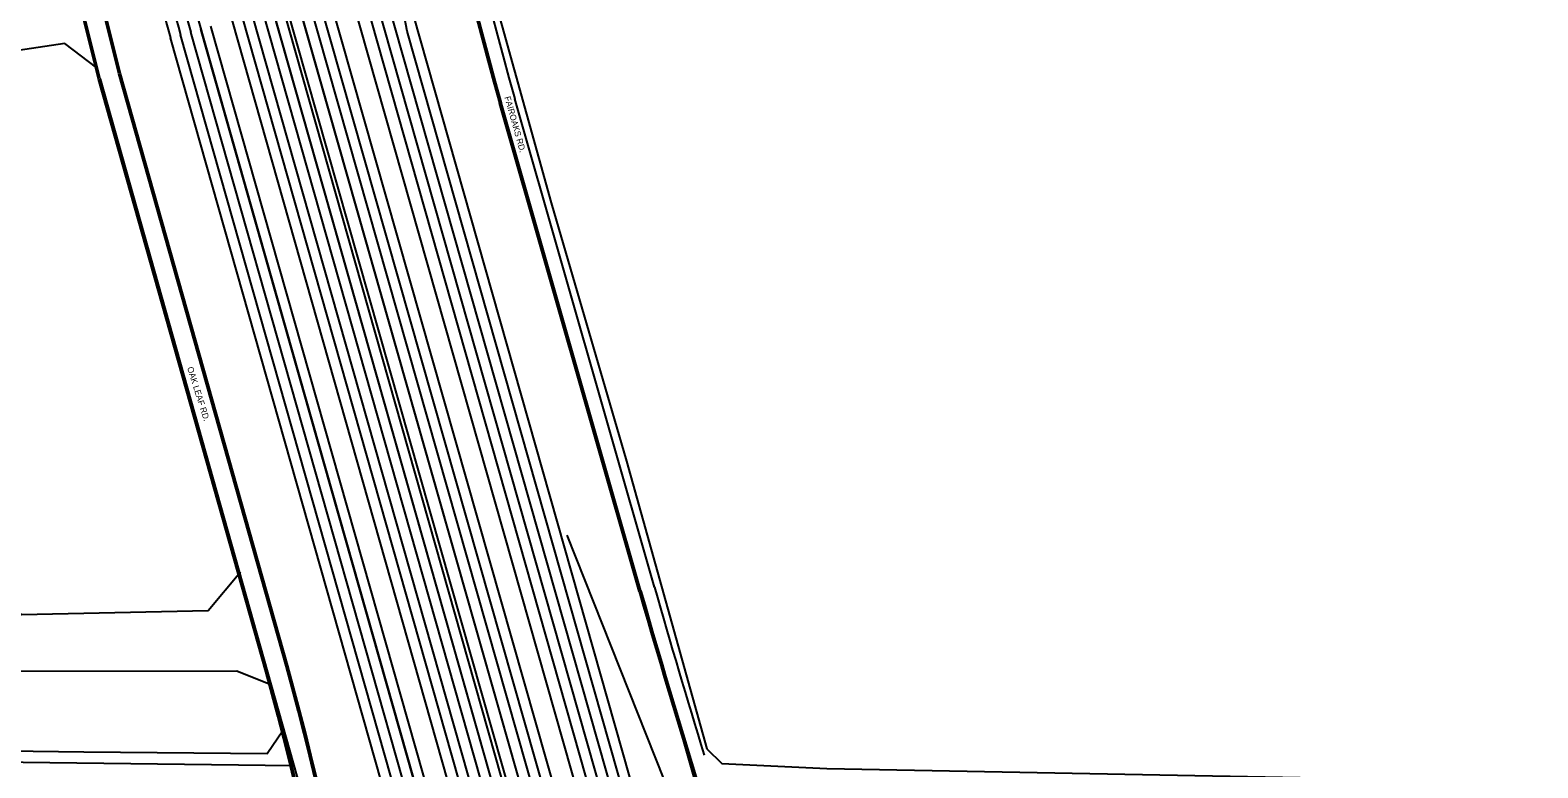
# Model space of a CAD drawing. Extents: x 227157 to 233208, y 434992 to 456232.
# Drawn here: x 228022 to 229741, y 441185 to 442026 of the extents above; entities that cross this region are included whole.
import ezdxf

# ---------------------------------------------------------------- set-up
doc = ezdxf.new("R2010")
doc.units = 0
for name, color, linetype in [('GE_X_Alignment', 7, 'Continuous'), ('PM_X_Edge_Line', 7, 'Continuous'), ('PM_X_Lane_Line', 7, 'Continuous'), ('PV_X_EOP', 7, 'Continuous'), ('SV_X_Text_Name', 7, 'Continuous')]:
    doc.layers.add(name, color=color, linetype=linetype)

msp = doc.modelspace()

# ---------------------------------------------------------------- linework, layer by layer
at = {"layer": 'GE_X_Alignment'}
for p, q in [((229741.1, 437351.7), (227977.9, 443563.5)), ((229633.3, 437464.5), (227927.6, 443466.1)), ((227851.2, 443315.4), (228989, 439305.6)), ((229609.5, 437429.5), (227988.9, 443142.3)), ((228939, 440614.9), (228424.6, 442414.9)), ((228102.1, 441970.7), (228482.9, 440620.6)), ((229099.2, 440282.1), (228634.2, 441450.4))]:
    msp.add_line(p, q, dxfattribs=at)
for centre, radius, start, end in [((232310.4, 443015.6), 3901.3, 184.177, 195.95), ((239163.9, 444372.1), 10863.7, 195.95, 201.69969), ((225496.6, 440506.4), 2905.1, 359.1873, 15.7485)]:
    msp.add_arc(centre, radius, start, end, dxfattribs=at)
at = {"layer": 'PM_X_Edge_Line'}
for p, q in [((228102.1, 441970.7), (228028.1, 442265.3)), ((228123.4, 441976.4), (228055.5, 442246.3)), ((228452, 442025.2), (228432, 442131.7)), ((229405.2, 438534.9), (228394.3, 442096.5)), ((229527.9, 437923.2), (228350.6, 442065.3)), ((229328.7, 438419.5), (228298.5, 442051)), ((229504.8, 437916.6), (228327.5, 442058.8)), ((228263.8, 442041.2), (229294, 438409.6)), ((228766.4, 440002.2), (228193.6, 442020.7)), ((228789.4, 440008.8), (228216.7, 442027.3)), ((229037.1, 439963.6), (228452, 442025.2)), ((228292.7, 441294.9), (228102.1, 441970.7)), ((228313.9, 441300.9), (228123.4, 441976.4)), ((228718.4, 441386.7), (228559.3, 441943.5)), ((228733.8, 441391.1), (228574.7, 441947.9)), ((227250, 441201), (228320.8, 441187.5))]:
    msp.add_line(p, q, dxfattribs=at)
for centre, radius, start, end in [((232310.4, 443015.6), 3901.3, 184.177, 195.95), ((232310.4, 443015.6), 3885.3, 184.177, 195.95), ((232085.6, 443125.1), 4045.6, 193.7392, 195.8413), ((239163.9, 444372.1), 10863.7, 195.95, 201.69969), ((239163.9, 444372.1), 10847.7, 195.95, 197.00557), ((225496.6, 440506.4), 2905.1, 359.1873, 15.7485), ((225496.6, 440506.4), 2927.1, 359.1873, 15.7485)]:
    msp.add_arc(centre, radius, start, end, dxfattribs=at)
at = {"layer": 'PM_X_Lane_Line'}
for p, q in [((229416.8, 438538.2), (228405.8, 442099.8)), ((229047.9, 439881.6), (228417.4, 442103.1)), ((228286.9, 442047.7), (229317.1, 438416.2)), ((228339.1, 442062.1), (229516.3, 437919.9)), ((229305.6, 438412.9), (228275.4, 442044.5)), ((228777.9, 440005.5), (228205.2, 442024))]:
    msp.add_line(p, q, dxfattribs=at)
msp.add_arc((232085.6, 443125.1), 4033.6, 165.7953, 195.8413, dxfattribs=at)
at = {"layer": 'PV_X_EOP'}
for p, q in [((228100.2, 441970.2), (228026.1, 442264.8)), ((228125.3, 441976.9), (228055.7, 442253.6)), ((229391.8, 438531.1), (228380.8, 442092.7)), ((229539.4, 437926.5), (228362.2, 442068.6)), ((229340.2, 438422.7), (228310, 442054.3)), ((229391.7, 438263.5), (228314.1, 442054.9)), ((228520.8, 440999.5), (228228.2, 442030.6)), ((229282.5, 438406.4), (228252.3, 442037.9)), ((229080.9, 439853.3), (228458.9, 442044.8)), ((228609.7, 440510.2), (228182.1, 442017.5)), ((228315.8, 441301.4), (228125.3, 441976.9)), ((228290.8, 441294.4), (228100.2, 441970.2)), ((228716.5, 441386.2), (228557.4, 441942.9))]:
    msp.add_line(p, q, dxfattribs=at)
for points in [[(228488.6, 442319.3), (228531.9, 442133), (228616.2, 441829.3), (228702, 441534.8), (228793.5, 441206.7)], [(228098.1, 441983.2), (228061.6, 442010.9), (227957.5, 441995.6), (227701.3, 441943.5), (227621.3, 441905), (227177.5, 441908)], [(227562.5, 441211.8), (227586.7, 441224.3), (227588, 441286.7), (227385.6, 441294.6), (227373.1, 441280.8), (227283, 441277.5), (227290.1, 441649.3), (227318.6, 441732.3), (227398.5, 441764.1), (227460, 441765.8), (227471.1, 441798.8), (227683.4, 441809.6), (227710, 441780.1), (227802.4, 441760.9), (227962.8, 441764.2), (227969.8, 441431.9), (227953.6, 441398.1), (228012.1, 441360), (228225.1, 441364.5), (228262.1, 441408.6)], [(228294.7, 441280.3), (228257.7, 441295.1), (227833.5, 441294.8), (227827.4, 441278.5), (227666.1, 441279.7), (227645.7, 441297.5), (227624.2, 441298.7), (227614.5, 441250.7), (227629.8, 441219.4), (227649.5, 441208.9), (228083.3, 441203.4), (228292.4, 441201.2), (228310.3, 441227.5)], [(228793.5, 441206.7), (228810.7, 441189.8), (228930.5, 441184.1), (229670.1, 441170)]]:
    msp.add_lwpolyline(points, dxfattribs=at)
for centre, radius, start, end in [((232310.4, 443015.6), 3903.3, 184.177, 195.95), ((232085.6, 443125.1), 4057.6, 190.1801, 195.8413), ((239163.9, 444372.1), 10865.7, 195.95, 201.69969), ((225496.6, 440506.4), 2903.1, 359.1873, 15.7485), ((225496.6, 440506.4), 2929.1, 359.1873, 15.7485)]:
    msp.add_arc(centre, radius, start, end, dxfattribs=at)

# ---------------------------------------------------------------- texts
at = {"layer": 'SV_X_Text_Name'}
for s, rotation, p in [('FAIROAKS RD.', 285.6702, (228562.8, 441949.7)), ('OAK LEAF RD.', 287.5141, (228201, 441641.1))]:
    msp.add_text(s, height=7, rotation=rotation, dxfattribs=at).set_placement(p)

doc.saveas('drawing.dxf')
